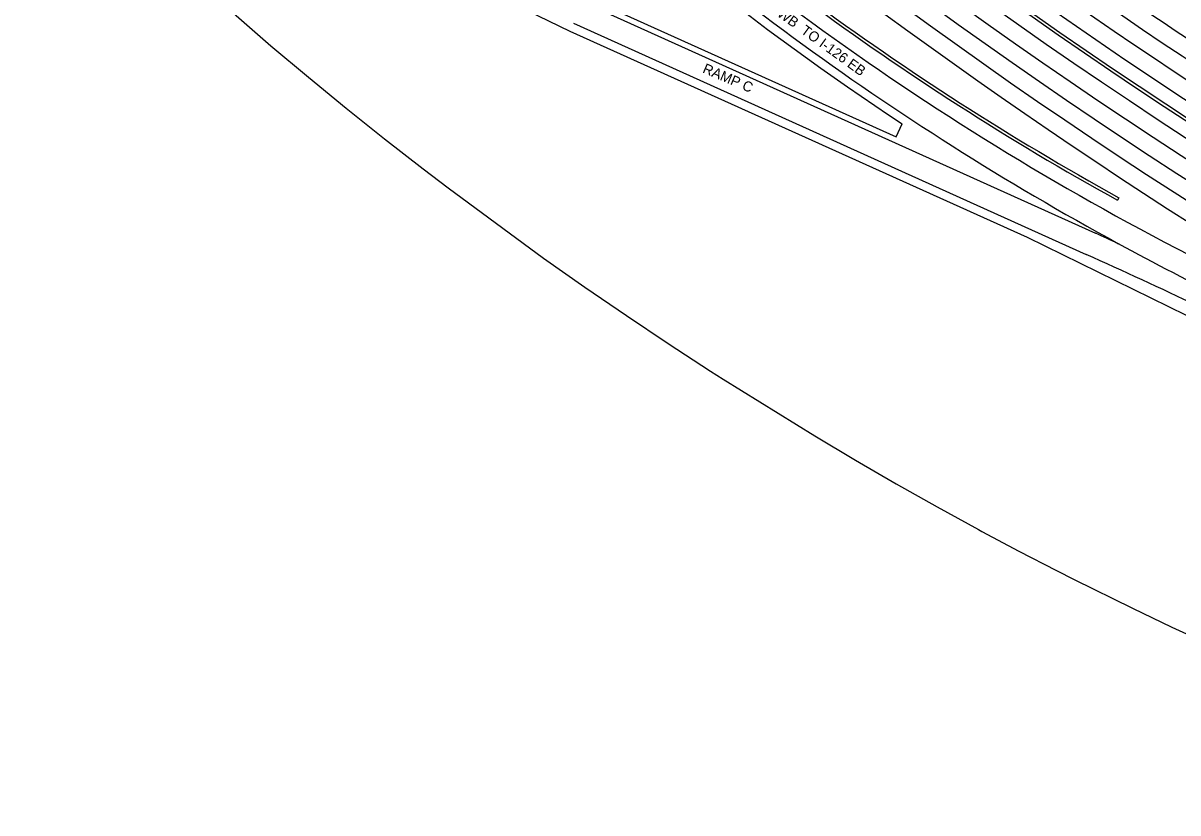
# Model space of a CAD drawing. Extents: x -5665 to 1997148, y 4 to 812485.
# Drawn here: x 1971404 to 1972202, y 794525 to 795072 of the extents above; entities that cross this region are included whole.
import ezdxf

# ---------------------------------------------------------------- set-up
doc = ezdxf.new("R2010")
doc.units = 0
for name, color, linetype in [('RD_EX_RailRoad', 7, 'Continuous'), ('RD_PD_ALT1_TrvlWay', 7, 'Continuous'), ('RD_PD_Final_LnLine', 7, 'Continuous'), ('RD_PD_MedBWall', 7, 'Continuous'), ('RD_PD_PaveShd', 7, 'Continuous'), ('RD_SHT_TX', 7, 'Continuous')]:
    doc.layers.add(name, color=color, linetype=linetype)

msp = doc.modelspace()

# ---------------------------------------------------------------- linework, layer by layer
at = {"layer": 'RD_EX_RailRoad'}
msp.add_lwpolyline([(1971512.52, 795110.76), (1971575.1, 795055.94), (1971601.02, 795034.25), (1971627.2, 795012.84), (1971653.63, 794991.73), (1971680.31, 794970.94), (1971697.68, 794957.67), (1971763.72, 794909.08), (1971792.22, 794889.07), (1971820.98, 794869.37), (1971849.95, 794850), (1971879.15, 794830.95), (1971887.96, 794825.3), (1971951.41, 794786.16), (1971979.4, 794769.44), (1972007.59, 794753.05), (1972035.98, 794737.01), (1972064.57, 794721.3), (1972066.88, 794720.05), (1972092.55, 794706.42), (1972118.4, 794693.13), (1972130.8, 794686.91), (1972171.08, 794667), (1972198.4, 794653.74), (1972240.53, 794634.77)], dxfattribs=at)
at = {"layer": 'RD_PD_ALT1_TrvlWay'}
for p, q in [((1971790.98, 795086.26), (1972145.53, 794926.28)), ((1971784.4, 795071.67), (1972138.95, 794911.7))]:
    msp.add_line(p, q, dxfattribs=at)
for centre, radius, start, end in [((1974296, 798203.94), 3808.72, 221.35099, 236.97136), ((1974296, 798203.94), 3830.72, 221.69794, 243.9112), ((1974296, 798203.94), 3878.72, 222.58465, 241.30888), ((1973117.1, 796675.98), 1984, 226.17145, 243.9112), ((1973117.1, 796675.98), 2000, 226.17145, 241.45743), ((1972948.57, 796040.02), 1200, 225.41147, 237.12717), ((1969913.96, 789980.42), 5426, 65.53025, 65.71509), ((1969913.96, 789980.42), 5410, 63.9112, 65.71509)]:
    msp.add_arc(centre, radius, start, end, dxfattribs=at)
at = {"layer": 'RD_PD_Final_LnLine'}
for centre, radius, start, end in [((1974296, 798203.94), 3784.72, 220.98219, 236.97136), ((1974296, 798203.94), 3796.72, 221.18106, 236.97136), ((1974296, 798203.94), 3842.72, 221.90557, 243.9112), ((1974296, 798203.94), 3854.72, 222.10892, 243.9112), ((1974296, 798203.94), 3866.72, 222.36815, 243.9112), ((1974296, 798203.94), 3772.72, 227.89927, 236.97136), ((1973117.1, 796675.98), 2000, 241.44655, 243.9112)]:
    msp.add_arc(centre, radius, start, end, dxfattribs=at)
at = {"layer": 'RD_PD_MedBWall'}
for radius, start in [(3820.72, 222.66541), (3818.72, 222.66592)]:
    msp.add_arc((1974296, 798203.94), radius, start, 243.9112, dxfattribs=at)
at = {"layer": 'RD_PD_PaveShd'}
for p, q in [((1971792.63, 795089.9), (1972007.59, 794992.91)), ((1971781.93, 795066.2), (1972098.21, 794923.5)), ((1972007.59, 794992.91), (1972011.7, 795002.03)), ((1972161.68, 794950.89), (1972160.71, 794949.14)), ((1972098.21, 794923.5), (1972911.31, 794525.36))]:
    msp.add_line(p, q, dxfattribs=at)
for centre, radius, start, end in [((1972046.23, 795651.96), 642.62, 156.21044, 245.71509), ((1973117.1, 796675.98), 1974, 226.17145, 241.02073), ((1973117.1, 796675.98), 1972, 226.17145, 241.02073), ((1973117.1, 796675.98), 2006, 226.17145, 236.56111), ((1972996.53, 796085.43), 1256, 225.41147, 239.13377)]:
    msp.add_arc(centre, radius, start, end, dxfattribs=at)

# ---------------------------------------------------------------- texts
at = {"layer": 'RD_SHT_TX'}
for s, rotation, p in [(' RAMP I-26 WB  TO I-126 EB', 324.11706, (1971883.37, 795106.88)), ('RAMP C', 336.9216, (1971873.17, 795037.64))]:
    msp.add_text(s, height=7, rotation=rotation, dxfattribs=at).set_placement(p)

doc.saveas('drawing.dxf')
